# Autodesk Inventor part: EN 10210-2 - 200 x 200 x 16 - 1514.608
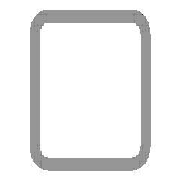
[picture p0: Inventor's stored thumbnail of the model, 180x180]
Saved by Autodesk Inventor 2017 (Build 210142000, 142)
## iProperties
_CCFamilyMember: 94
_CCFamilyDisplayName: DIN EN 10210-2 (Square) - Tube — Sizes in parentheses have been withdrawn
_FrameMemberDoc: Frame Member File
_Version: 15.0.0
_GetPNFromCC: 1
Created: 2017-11
Part Number: EN 10210-2 - 200 x 200 x 16 - 1514.608
Material: Steel, Mild
Description: Tube
Document SubType Name: Modeling
Standard: DIN
Designer: iusti
Standard Revision: 2006-07
Standards Organization: DIN
Language: en-US
Size Designation: 200 x 200 x 16
Categories: <MemberInstance><Categories><Category DisplayName="Structural Shapes" InternalName="089c4875-fa83-4c05-b084-43b9cc11f5ed" Mnemonic="GRDR"><CategoryParameter Dis
Stock Number: 200 x 200 x 16
Density: 7.85 g/cm^3
Appearance: Semi-Polished
Mass: 136747 g
Surface Area: 21484.9 cm^2
Volume: 17420 cm^3
IsCustomPart: 1
G_L: 1514.608 mm
G_W: 200.000 mm
G_H: 200.000 mm
+C5C6E196-79AF-46FD-B532-9DED2DA3D966+CUTDETAIL1: Cut
Author: iusti
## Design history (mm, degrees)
node "Start plane"
node "End plane"
sketch "Sketch"
  geometry: L1 (-100, -76)-(-100, 76); L2 (-76, 100)-(76, 100); L3 (100, 76)-(100, -76); L4 (76, -100)-(-76, -100); L5 (-68, 84)-(68, 84); L6 (84, 68)-(84, -68); L7 (68, -84)-(-68, -84); L8 (-84, -68)-(-84, 68); L9 (0, 146.959)-(0, -146.959) reference; L10 (-146.959, 0)-(146.959, 0) reference; A1 r 24 centre (-76, -76) between (-100, -76) and (-76, -100); A2 r 24 centre (-76, 76) between (-76, 100) and (-100, 76); A3 r 24 centre (76, 76) between (100, 76) and (76, 100); A4 r 24 centre (76, -76) between (76, -100) and (100, -76); A5 r 16 centre (-68, -68) between (-84, -68) and (-68, -84); A6 r 16 centre (-68, 68) between (-68, 84) and (-84, 68); A7 r 16 centre (68, 68) between (84, 68) and (68, 84); A8 r 16 centre (68, -68) between (68, -84) and (84, -68)
  constraints: 16 end point, 16 point on circle, 16 tangent, 8 centre point, 6 equal radius, 4 parallel, 2 perpendicular, 2 other
  dimensions: "d7" = 24 radius of A1 (= G_IR); "d10" = 200 distance between parallel lines of L2 L4 (= G_H); "d11" = 200 distance between parallel lines of L1 L3 (= G_W); "d12" = 16 distance between parallel lines of L3 L6 (= G_T); "d15" = 100 distance between parallel lines of L2 L10 (= 0.5 x d10); "d16" = 100 distance between parallel lines of L9 L3 (= 0.5 x d11); "d19" = 16 radius of A5 (= G_T); "d20" = 16 distance between parallel lines of L4 L7 (= G_T)
extrude "Body" new body sketch "Sketch" stored distance "d3" = 1514.60835 (= G_L); taper "d4" = 0 deg
node "Driven Length"
  sketch "Sketch3"
    geometry: L1 (0, 0)-(10, 0) reference
    constraints: 2 end point, 1 horizontal
  workplane "Work Plane3"
  sketch "Sketch4"
    geometry: L1 (-2, 0)-(12, 0) reference; L2 (-2, 1514.608)-(12, 1514.608) reference
    dimensions: "d18" = 1514.60835 distance between parallel lines of L1 L2 (derived)
workplane "Work Plane4"
split "Split1"
body "Solid1"
other parameters: "G_W" = 200 [user parameter; used in 1 equation term], "G_H" = 200 [user parameter; used in 1 equation term], "G_T" = 16 [user parameter; used in 3 equation terms], "G_IR" = 24 [user parameter; used in 1 equation term], "G_L" = 1514.60835 (= d18) [user parameter; used in 1 equation term], "G_OFFSET_START" = 0 [user parameter; used in 1 equation term], "d13" = 0 (computed from G_OFFSET_START), "d14" = 1514.60835 (= G_OFFSET_END + B_L), "B_L" = 1614.60835 [user parameter; used in 1 equation term], "d17" = 90 deg
